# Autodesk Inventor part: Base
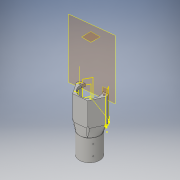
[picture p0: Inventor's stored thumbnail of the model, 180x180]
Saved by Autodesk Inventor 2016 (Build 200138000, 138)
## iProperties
Created: 2015-09
Part Number: Base
Material: Generic
Document SubType Name: Modeling
Designer: Z
Density: 1 g/cm^3
Appearance: Default
Author: Z
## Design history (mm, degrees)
derived "cane mount.ipt"
  sketch "Sketch37"
    geometry: L1 (7.76, 0)-(8.043, 0) reference; L2 (19.064, 57.15)-(19.064, 0) reference; L3 (15.314, 0)-(15.314, 50.8) reference; L4 (15.314, 50.8)-(8.043, 50.8) reference; L5 (8.043, 0)-(8.043, 50.8) reference; L6 (8.043, 57.15)-(19.064, 57.15) reference; L7 (8.043, 50.8)-(8.043, 57.15) reference; L8 (0, 50.8)-(0, 0) reference; L9 (7.76, 50.8)-(7.76, 0) reference; L10 (7.76, 50.8)-(0, 50.8) reference; L11 (-3.767, 0)-(-3.767, 63.5) reference; L12 (-3.767, 63.5)-(7.76, 63.5) reference; L13 (7.76, 63.5)-(7.76, 50.8) reference; L14 (15.314, 3.175)-(0, 3.175) reference; L15 (0, 3.175)-(0, 15.875) reference; L16 (0, 15.875)-(15.314, 15.875) reference; L17 (15.314, 15.875)-(15.314, 3.175) reference; 5 further points
  sketch "Sketch38"
    geometry: L1 (-12.361, 64.822)-(-4.847, 64.822) reference; L2 (-4.847, 64.822)-(7.871, 9.897) reference; L3 (7.871, 9.897)-(5.044, 0.782) reference; L4 (-56.252, 0.782)-(-58.671, 11.761) reference; L5 (-58.671, 11.761)-(-43.805, 64.822) reference; L6 (-43.805, 64.822)-(-37.173, 64.822) reference; L7 (-40.964, 57.706)-(-42.061, 57.706) reference; L8 (-42.061, 57.706)-(-55.048, 11.353) reference; L9 (-55.048, 11.353)-(-52.719, 0.782) reference; L10 (1.192, 0.782)-(4.181, 10.421) reference; L11 (4.181, 10.421)-(-6.768, 57.706) reference; L12 (-6.768, 57.706)-(-8.569, 57.706) reference; L13 (-24.767, 23.835)-(-24.767, -28.939) reference; C1 r 1.5 at (-24.767, -22.589) reference; 14 further points; 3 other entities
    constraints: 3 other
  sketch "Sketch39"
    geometry: L1 (-25.388, 57.15)-(-14.362, 57.15) reference; L2 (-14.362, 57.15)-(-14.362, 50.8) reference; L3 (-14.362, 50.8)-(-14.362, 0) reference; L4 (-14.362, 0)-(-14.4, 0) reference; L5 (-21.781, 50.8)-(-21.781, 0) reference; L6 (-14.362, 50.8)-(-21.781, 50.8) reference; L7 (-25.388, 0.007)-(-25.388, 57.15) reference; L8 (-14.4, 0)-(-7.597, -10.524) reference; L9 (-7.597, -10.524)-(-14.054, 0) reference; L10 (0, 50.8)-(-14.054, 50.8) reference; L11 (-14.054, 0)-(-14.054, 50.8) reference; L12 (-14.054, 50.8)-(-14.054, 63.5) reference; L13 (-14.054, 63.5)-(3.595, 63.5) reference; L14 (3.595, 63.5)-(3.595, 0.004) reference; L15 (0, 0)-(0, 50.8) reference; L16 (-21.781, 25.4)-(0, 25.4) reference; L17 (0, 25.4)-(0, 6.35) reference; L18 (0, 6.35)-(-21.781, 6.35) reference; L19 (-21.781, 6.35)-(-21.781, 25.4) reference; 3 further points
feature "Solid14::cane mount.ipt" dims "d0" = 10
tag "TaggingFeature1"
workplane "Work Plane6"
workplane "Work Plane7"
workplane "Work Plane14"
workaxis "Work Axis2"
body "Solid1"
